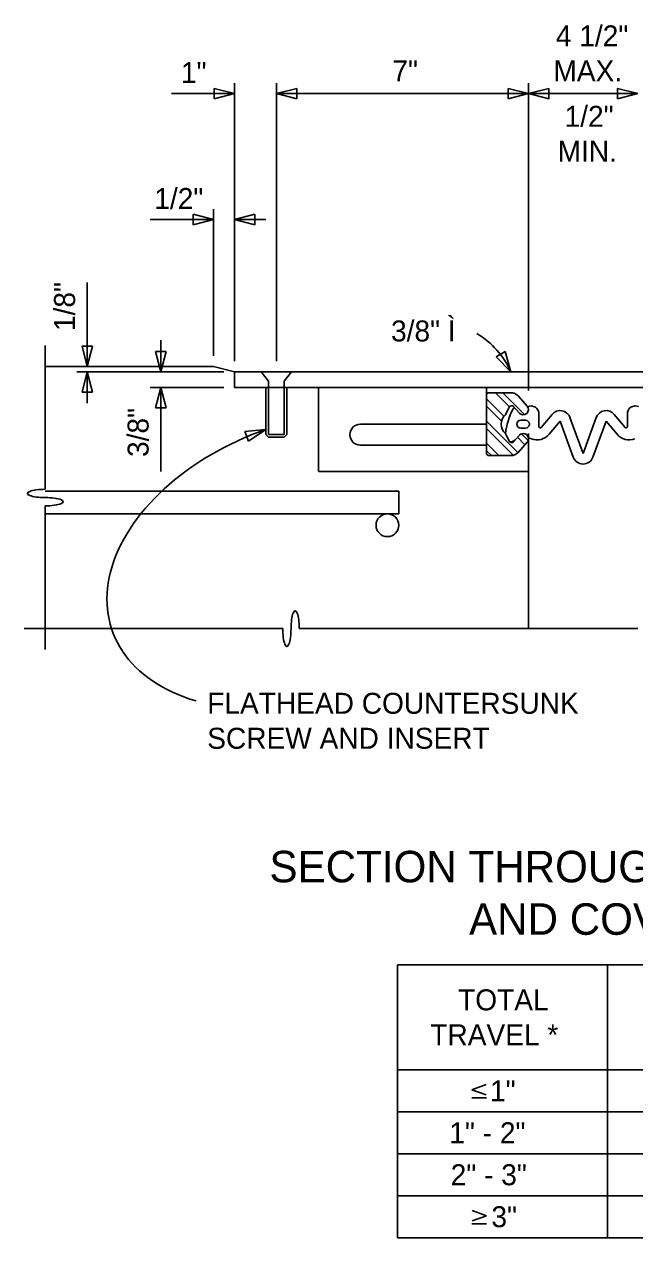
# Model space of a CAD drawing. Extents: x 19590 to 20151, y 19944 to 20103.
# Drawn here: x 19678.31 to 19691.75, y 20042.3 to 20069.04 of the extents above; entities that cross this region are included whole.
import ezdxf

# ---------------------------------------------------------------- set-up
doc = ezdxf.new("R2010")
doc.units = 0
for name, color, linetype in [('B-O', 7, 'Continuous'), ('Default', 7, 'Continuous'), ('DETAIL_PR', 7, 'Continuous'), ('DETAIL_TEXT_DIMEN_PR', 7, 'Continuous'), ('Level 1', 7, 'Continuous'), ('Sheet_Label_Str_Wt0', 7, 'Continuous')]:
    doc.layers.add(name, color=color, linetype=linetype)

# ---------------------------------------------------------------- blocks, each defined once
blk = doc.blocks.new('_X7')
at = {"layer": 'Default'}
for p, q in [((8.051, 16.889), (8.594, 17.433)), ((8.426, 17.08), (8.778, 17.433)), ((8.56, 16.847), (8.995, 17.282)), ((8.622, 16.724), (8.995, 17.098)), ((8.213, 15.947), (8.995, 16.729)), ((7.96, 16.247), (8.125, 16.412)), ((8.04, 16.142), (8.224, 16.326)), ((8.329, 15.879), (8.995, 16.545)), ((8.689, 15.87), (8.995, 16.177)), ((8.873, 15.87), (8.995, 15.993))]:
    blk.add_line(p, q, dxfattribs=at)

msp = doc.modelspace()

# ---------------------------------------------------------------- linework, layer by layer
at = {"layer": 'B-O'}
msp.add_line((19684.787, 20061.036), (19688.545, 20061.036), dxfattribs=at)
msp.add_line((19684.787, 20061.036), (19688.545, 20061.036), dxfattribs=at)
at = {"layer": 'DETAIL_PR'}
for p, q in [((19682.475, 20061.498), (19678.775, 20061.498)), ((19682.475, 20061.498), (19678.775, 20061.498)), ((19682.937, 20061.383), (19682.475, 20061.498)), ((19682.937, 20061.383), (19682.475, 20061.498)), ((19682.937, 20061.036), (19682.937, 20061.383)), ((19682.937, 20061.383), (19699.472, 20061.383)), ((19682.937, 20061.036), (19682.937, 20061.383)), ((19682.937, 20061.383), (19699.472, 20061.383)), ((19683.689, 20061.176), (19683.531, 20061.383)), ((19683.531, 20061.383), (19684.194, 20061.383)), ((19683.689, 20061.176), (19683.531, 20061.383)), ((19683.531, 20061.383), (19684.194, 20061.383)), ((19684.194, 20061.383), (19684.036, 20061.176)), ((19684.194, 20061.383), (19684.036, 20061.176)), ((19683.689, 20059.995), (19683.689, 20061.176)), ((19683.689, 20059.995), (19683.689, 20061.176)), ((19684.036, 20061.176), (19684.036, 20059.995)), ((19684.036, 20061.176), (19684.036, 20059.995)), ((19699.587, 20061.036), (19682.937, 20061.036)), ((19699.587, 20061.036), (19682.937, 20061.036)), ((19683.631, 20059.995), (19683.631, 20061.036)), ((19683.631, 20059.995), (19683.631, 20061.036)), ((19684.094, 20061.036), (19684.094, 20059.995)), ((19684.094, 20061.036), (19684.094, 20059.995)), ((19684.787, 20059.186), (19684.787, 20061.036)), ((19684.787, 20059.186), (19684.787, 20061.036)), ((19688.487, 20060.862), (19688.487, 20061.036)), ((19688.487, 20060.862), (19688.487, 20061.036)), ((19688.487, 20060.862), (19688.487, 20060.226)), ((19688.487, 20060.862), (19688.487, 20060.226)), ((19689.019, 20060.92), (19688.545, 20060.92)), ((19689.019, 20060.92), (19688.545, 20060.92)), ((19688.904, 20060.43), (19688.991, 20060.602)), ((19688.904, 20060.43), (19688.991, 20060.602)), ((19689.21, 20060.473), (19689.085, 20060.614)), ((19689.21, 20060.473), (19689.085, 20060.614)), ((19689.383, 20060.626), (19689.192, 20060.842)), ((19689.383, 20060.626), (19689.192, 20060.842)), ((19689.242, 20060.313), (19689.347, 20060.313)), ((19689.242, 20060.313), (19689.347, 20060.313)), ((19689.64, 20060.443), (19689.64, 20060.174)), ((19689.64, 20060.443), (19689.64, 20060.174)), ((19689.691, 20060.155), (19689.933, 20060.442)), ((19689.691, 20060.155), (19689.933, 20060.442)), ((19690.616, 20059.578), (19690.327, 20060.373)), ((19690.616, 20059.578), (19690.327, 20060.373)), ((19690.616, 20059.578), (19690.905, 20060.373)), ((19690.616, 20059.578), (19690.905, 20060.373)), ((19691.541, 20060.155), (19691.3, 20060.442)), ((19691.541, 20060.155), (19691.3, 20060.442)), ((19691.592, 20060.443), (19691.592, 20060.174)), ((19691.592, 20060.443), (19691.592, 20060.174)), ((19688.487, 20060.226), (19685.712, 20060.226)), ((19688.487, 20060.226), (19685.712, 20060.226)), ((19688.487, 20060.226), (19688.487, 20059.764)), ((19688.487, 20060.226), (19688.487, 20059.764)), ((19689.242, 20060.14), (19689.347, 20060.14)), ((19689.242, 20060.14), (19689.347, 20060.14)), ((19689.866, 20060.003), (19690.11, 20060.294)), ((19689.866, 20060.003), (19690.11, 20060.294)), ((19690.399, 20059.499), (19690.11, 20060.294)), ((19690.399, 20059.499), (19690.11, 20060.294)), ((19690.833, 20059.499), (19691.122, 20060.294)), ((19690.833, 20059.499), (19691.122, 20060.294)), ((19691.366, 20060.003), (19691.122, 20060.294)), ((19691.366, 20060.003), (19691.122, 20060.294)), ((19683.631, 20059.995), (19683.689, 20059.937)), ((19683.631, 20059.995), (19683.689, 20059.937)), ((19684.036, 20059.995), (19683.689, 20059.995)), ((19684.036, 20059.995), (19683.689, 20059.995)), ((19684.036, 20059.937), (19683.689, 20059.937)), ((19684.036, 20059.937), (19683.689, 20059.937)), ((19684.094, 20059.995), (19684.036, 20059.937)), ((19684.094, 20059.995), (19684.036, 20059.937)), ((19688.904, 20060.023), (19688.991, 20059.851)), ((19688.904, 20060.023), (19688.991, 20059.851)), ((19689.121, 20059.879), (19689.078, 20059.854)), ((19689.121, 20059.879), (19689.078, 20059.854)), ((19689.21, 20059.98), (19689.085, 20059.839)), ((19689.21, 20059.98), (19689.085, 20059.839)), ((19689.383, 20059.827), (19689.192, 20059.611)), ((19689.383, 20059.827), (19689.192, 20059.611)), ((19689.48, 20059.9), (19689.41, 20059.926)), ((19689.48, 20059.9), (19689.41, 20059.926)), ((19689.412, 20055.72), (19689.412, 20060.019)), ((19689.412, 20055.72), (19689.412, 20060.019)), ((19688.487, 20059.764), (19685.712, 20059.764)), ((19688.487, 20059.764), (19685.712, 20059.764)), ((19688.487, 20059.764), (19688.487, 20059.591)), ((19688.487, 20059.764), (19688.487, 20059.591)), ((19688.545, 20059.533), (19689.019, 20059.533)), ((19688.545, 20059.533), (19689.019, 20059.533)), ((19689.412, 20059.186), (19684.799, 20059.186)), ((19689.412, 20059.186), (19684.799, 20059.186)), ((19678.775, 20058.748), (19686.557, 20058.748)), ((19678.775, 20058.748), (19686.557, 20058.748)), ((19686.557, 20058.748), (19686.557, 20058.248)), ((19686.557, 20058.748), (19686.557, 20058.248)), ((19678.775, 20058.248), (19686.557, 20058.248)), ((19678.775, 20058.248), (19686.557, 20058.248))]:
    msp.add_line(p, q, dxfattribs=at)
msp.add_circle((19686.307, 20057.998), 0.25, dxfattribs=at)
msp.add_circle((19686.307, 20057.998), 0.25, dxfattribs=at)
for centre, radius, start, end in [((19688.545, 20060.862), 0.0578, 90, 180), ((19688.545, 20060.862), 0.0578, 90, 180), ((19689.019, 20060.689), 0.231, 41.462, 90), ((19689.019, 20060.689), 0.231, 41.462, 90), ((19689.042, 20060.576), 0.0578, 41.462, 153.1909), ((19689.042, 20060.576), 0.0578, 41.462, 153.1909), ((19689.125, 20060.533), 0.0578, 106.6655, 151.2528), ((19689.125, 20060.533), 0.0578, 106.6655, 151.2528), ((19689.297, 20060.549), 0.116, 221.462, 41.462), ((19689.297, 20060.549), 0.116, 221.462, 41.462), ((19689.468, 20060.456), 0.173, 355.6455, 115.2375), ((19689.468, 20060.456), 0.173, 355.6455, 115.2375), ((19691.765, 20060.456), 0.173, 64.7625, 184.3545), ((19691.765, 20060.456), 0.173, 64.7625, 184.3545), ((19689.081, 20060.226), 0.27, 131.1121, 228.8879), ((19689.081, 20060.226), 0.27, 131.1121, 228.8879), ((19690.291, 20059.893), 1.388, 151.2528, 175.0143), ((19690.291, 20059.893), 1.388, 151.2528, 175.0143), ((19689.242, 20060.226), 0.0867, 90, 270), ((19689.242, 20060.226), 0.0867, 90, 270), ((19689.347, 20060.226), 0.0867, 270, 90), ((19689.347, 20060.226), 0.0867, 270, 90), ((19690.11, 20060.294), 0.231, 19.9948, 140), ((19690.11, 20060.294), 0.231, 19.9948, 140), ((19691.122, 20060.294), 0.231, 40, 160.0052), ((19691.122, 20060.294), 0.231, 40, 160.0052), ((19685.712, 20059.995), 0.231, 90, 270), ((19685.712, 20059.995), 0.231, 90, 270), ((19689.669, 20060.174), 0.0289, 180, 320), ((19689.669, 20060.174), 0.0289, 180, 320), ((19691.563, 20060.174), 0.0289, 220, 0), ((19691.563, 20060.174), 0.0289, 220, 0), ((19689.042, 20059.877), 0.0578, 206.8091, 318.538), ((19689.042, 20059.877), 0.0578, 206.8091, 318.538), ((19689.02, 20059.954), 0.116, 258.4931, 300), ((19689.02, 20059.954), 0.116, 258.4931, 300), ((19689.297, 20059.904), 0.116, 0, 138.538), ((19689.297, 20059.904), 0.116, 0, 138.538), ((19689.297, 20059.904), 0.116, 318.538, 0), ((19689.297, 20059.904), 0.116, 318.538, 0), ((19689.6, 20060.226), 0.347, 249.847, 320), ((19689.6, 20060.226), 0.347, 249.847, 320), ((19691.632, 20060.226), 0.347, 220, 290.153), ((19691.632, 20060.226), 0.347, 220, 290.153), ((19688.545, 20059.591), 0.0578, 180, 270), ((19688.545, 20059.591), 0.0578, 180, 270), ((19689.019, 20059.764), 0.231, 270, 318.538), ((19689.019, 20059.764), 0.231, 270, 318.538), ((19690.616, 20059.578), 0.231, 200, 340), ((19690.616, 20059.578), 0.231, 200, 340)]:
    msp.add_arc(centre, radius, start, end, dxfattribs=at)
for centre, major_axis, ratio, start_param, end_param in [((19678.775, 20058.7), (0.395, 0), 0.230204, 1.570796, 4.712389), ((19678.775, 20058.7), (0.395, 0), 0.230204, 1.570796, 4.712389), ((19678.775, 20058.518), (0.395, 0), 0.230206, 4.712389, 7.853982), ((19678.775, 20058.518), (0.395, 0), 0.230206, 4.712389, 7.853982), ((19684.276, 20055.72), (0, -0.395), 0.230204, 1.570796, 4.712389), ((19684.276, 20055.72), (0, -0.395), 0.230204, 1.570796, 4.712389), ((19684.094, 20055.72), (0, -0.395), 0.230206, 4.712389, 7.853982), ((19684.094, 20055.72), (0, -0.395), 0.230206, 4.712389, 7.853982)]:
    msp.add_ellipse(centre, major_axis=major_axis, ratio=ratio, start_param=start_param, end_param=end_param, dxfattribs=at)
at = {"layer": 'DETAIL_TEXT_DIMEN_PR'}
for p, q in [((19682.49, 20067.395), (19682.49, 20067.626)), ((19682.49, 20067.626), (19682.937, 20067.511)), ((19682.49, 20067.395), (19682.49, 20067.626)), ((19682.49, 20067.626), (19682.937, 20067.511)), ((19682.937, 20061.614), (19682.937, 20067.742)), ((19682.937, 20061.614), (19682.937, 20067.742)), ((19683.862, 20061.614), (19683.862, 20067.742)), ((19683.862, 20061.614), (19683.862, 20067.742)), ((19684.31, 20067.626), (19683.862, 20067.511)), ((19684.31, 20067.626), (19683.862, 20067.511)), ((19684.31, 20067.395), (19684.31, 20067.626)), ((19684.31, 20067.395), (19684.31, 20067.626)), ((19688.965, 20067.395), (19688.965, 20067.626)), ((19688.965, 20067.626), (19689.412, 20067.511)), ((19688.965, 20067.395), (19688.965, 20067.626)), ((19688.965, 20067.626), (19689.412, 20067.511)), ((19689.412, 20060.967), (19689.412, 20067.742)), ((19689.412, 20060.967), (19689.412, 20067.742)), ((19689.86, 20067.626), (19689.412, 20067.511)), ((19689.86, 20067.626), (19689.412, 20067.511)), ((19689.86, 20067.395), (19689.86, 20067.626)), ((19689.86, 20067.395), (19689.86, 20067.626)), ((19691.372, 20067.395), (19691.372, 20067.626)), ((19691.372, 20067.626), (19691.82, 20067.511)), ((19691.372, 20067.395), (19691.372, 20067.626)), ((19691.372, 20067.626), (19691.82, 20067.511)), ((19682.937, 20067.511), (19682.49, 20067.395)), ((19682.937, 20067.511), (19682.49, 20067.395)), ((19689.412, 20067.511), (19683.862, 20067.511)), ((19683.862, 20067.511), (19684.31, 20067.395)), ((19689.412, 20067.511), (19683.862, 20067.511)), ((19683.862, 20067.511), (19684.31, 20067.395)), ((19689.412, 20067.511), (19688.965, 20067.395)), ((19689.412, 20067.511), (19688.965, 20067.395)), ((19689.412, 20067.511), (19691.82, 20067.511)), ((19689.412, 20067.511), (19689.86, 20067.395)), ((19689.412, 20067.511), (19691.82, 20067.511)), ((19689.412, 20067.511), (19689.86, 20067.395)), ((19691.82, 20067.511), (19691.372, 20067.395)), ((19691.82, 20067.511), (19691.372, 20067.395)), ((19682.475, 20061.73), (19682.475, 20064.967)), ((19682.475, 20061.73), (19682.475, 20064.967)), ((19682.027, 20064.62), (19682.027, 20064.851)), ((19682.027, 20064.851), (19682.475, 20064.736)), ((19682.027, 20064.62), (19682.027, 20064.851)), ((19682.027, 20064.851), (19682.475, 20064.736)), ((19682.475, 20064.736), (19682.027, 20064.62)), ((19682.475, 20064.736), (19682.027, 20064.62)), ((19683.385, 20064.851), (19682.937, 20064.736)), ((19683.385, 20064.851), (19682.937, 20064.736)), ((19682.937, 20064.736), (19683.385, 20064.62)), ((19682.937, 20064.736), (19683.385, 20064.62)), ((19683.385, 20064.62), (19683.385, 20064.851)), ((19683.385, 20064.62), (19683.385, 20064.851)), ((19678.775, 20058.791), (19678.775, 20061.961)), ((19678.775, 20058.791), (19678.775, 20061.961)), ((19679.584, 20061.946), (19679.816, 20061.946)), ((19679.7, 20061.498), (19679.584, 20061.946)), ((19679.584, 20061.946), (19679.816, 20061.946)), ((19679.7, 20061.498), (19679.584, 20061.946)), ((19679.816, 20061.946), (19679.7, 20061.498)), ((19679.816, 20061.946), (19679.7, 20061.498)), ((19681.203, 20061.831), (19681.434, 20061.831)), ((19681.319, 20061.383), (19681.203, 20061.831)), ((19681.203, 20061.831), (19681.434, 20061.831)), ((19681.319, 20061.383), (19681.203, 20061.831)), ((19681.434, 20061.831), (19681.319, 20061.383)), ((19681.434, 20061.831), (19681.319, 20061.383)), ((19688.699, 20061.711), (19688.899, 20061.828)), ((19688.699, 20061.711), (19688.899, 20061.828)), ((19689.026, 20061.383), (19688.699, 20061.711)), ((19689.026, 20061.383), (19688.699, 20061.711)), ((19688.899, 20061.828), (19689.026, 20061.383)), ((19688.899, 20061.828), (19689.026, 20061.383)), ((19682.706, 20061.383), (19679.469, 20061.383)), ((19682.706, 20061.383), (19679.469, 20061.383)), ((19679.584, 20060.935), (19679.7, 20061.383)), ((19679.584, 20060.935), (19679.7, 20061.383)), ((19679.7, 20061.383), (19679.816, 20060.935)), ((19679.7, 20061.383), (19679.816, 20060.935)), ((19679.816, 20060.935), (19679.584, 20060.935)), ((19679.816, 20060.935), (19679.584, 20060.935)), ((19682.706, 20061.036), (19681.087, 20061.036)), ((19682.706, 20061.036), (19681.087, 20061.036)), ((19681.203, 20060.588), (19681.319, 20061.036)), ((19681.203, 20060.588), (19681.319, 20061.036)), ((19681.319, 20061.036), (19681.434, 20060.588)), ((19681.319, 20061.036), (19681.434, 20060.588)), ((19681.434, 20060.588), (19681.203, 20060.588)), ((19681.434, 20060.588), (19681.203, 20060.588)), ((19683.171, 20060.066), (19683.631, 20060.112)), ((19683.171, 20060.066), (19683.631, 20060.112)), ((19683.251, 20059.849), (19683.171, 20060.066)), ((19683.251, 20059.849), (19683.171, 20060.066)), ((19683.631, 20060.112), (19683.251, 20059.849)), ((19683.631, 20060.112), (19683.251, 20059.849)), ((19678.775, 20055.258), (19678.775, 20058.427)), ((19678.775, 20055.258), (19678.775, 20058.427)), ((19678.312, 20055.72), (19684.003, 20055.72)), ((19678.312, 20055.72), (19684.003, 20055.72)), ((19689.412, 20055.72), (19684.367, 20055.72)), ((19689.412, 20055.72), (19684.367, 20055.72)), ((19686.526, 20048.311), (19686.526, 20042.298)), ((19686.526, 20048.311), (19700.401, 20048.311)), ((19686.526, 20048.311), (19686.526, 20042.298)), ((19686.526, 20048.311), (19700.401, 20048.311)), ((19691.151, 20048.311), (19691.151, 20042.298)), ((19691.151, 20048.311), (19691.151, 20042.298)), ((19686.526, 20045.998), (19700.401, 20045.998)), ((19686.526, 20045.998), (19700.401, 20045.998)), ((19688.166, 20045.559), (19688.481, 20045.674)), ((19688.166, 20045.559), (19688.481, 20045.674)), ((19688.166, 20045.559), (19688.481, 20045.445)), ((19688.166, 20045.559), (19688.481, 20045.445)), ((19688.166, 20045.382), (19688.49, 20045.382)), ((19688.166, 20045.382), (19688.49, 20045.382)), ((19686.526, 20045.073), (19700.401, 20045.073)), ((19686.526, 20045.073), (19700.401, 20045.073)), ((19686.526, 20044.148), (19700.401, 20044.148)), ((19686.526, 20044.148), (19700.401, 20044.148)), ((19686.526, 20043.223), (19700.401, 20043.223)), ((19686.526, 20043.223), (19700.401, 20043.223)), ((19688.49, 20042.784), (19688.175, 20042.899)), ((19688.49, 20042.784), (19688.175, 20042.899)), ((19688.49, 20042.784), (19688.175, 20042.67)), ((19688.49, 20042.784), (19688.175, 20042.67)), ((19688.49, 20042.607), (19688.166, 20042.607)), ((19688.49, 20042.607), (19688.166, 20042.607)), ((19686.526, 20042.298), (19700.401, 20042.298)), ((19686.526, 20042.298), (19700.401, 20042.298))]:
    msp.add_line(p, q, dxfattribs=at)
at = {"layer": 'Level 1'}
for p, q in [((19681.55, 20067.511), (19682.937, 20067.511)), ((19681.55, 20067.511), (19682.937, 20067.511)), ((19681.087, 20064.736), (19682.475, 20064.736)), ((19681.087, 20064.736), (19682.475, 20064.736)), ((19683.631, 20064.736), (19682.937, 20064.736)), ((19683.631, 20064.736), (19682.937, 20064.736)), ((19679.7, 20061.498), (19679.7, 20063.348)), ((19679.7, 20061.498), (19679.7, 20063.348)), ((19681.319, 20062.076), (19681.319, 20061.383)), ((19681.319, 20062.076), (19681.319, 20061.383)), ((19679.7, 20060.689), (19679.7, 20061.383)), ((19679.7, 20060.689), (19679.7, 20061.383)), ((19681.319, 20061.036), (19681.319, 20059.186)), ((19681.319, 20061.036), (19681.319, 20059.186)), ((19689.412, 20055.72), (19691.82, 20055.72)), ((19689.412, 20055.72), (19691.82, 20055.72))]:
    msp.add_line(p, q, dxfattribs=at)
msp.add_arc((19687.32, 20060.615), 1.87, 24.225, 59.1642, dxfattribs=at)
msp.add_arc((19687.32, 20060.615), 1.87, 24.225, 59.1642, dxfattribs=at)
msp.add_ellipse((19684.645, 20057.22), major_axis=(4.397, 1.542), ratio=0.657723, start_param=1.570796, end_param=3.885568, dxfattribs=at)
msp.add_ellipse((19684.645, 20057.22), major_axis=(4.397, 1.542), ratio=0.657723, start_param=1.570796, end_param=3.885568, dxfattribs=at)

# ---------------------------------------------------------------- block references
at = {"layer": 'DETAIL_PR', "xscale": 0.8880107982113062, "yscale": -0.8880107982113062, "rotation": 180}
msp.add_blockref('_X7', (19696.475, 20045.44), dxfattribs=at)
msp.add_blockref('_X7', (19696.475, 20045.44), dxfattribs=at)

# ---------------------------------------------------------------- texts
at = {"layer": 'DETAIL_TEXT_DIMEN_PR'}
for s, height, p in [('4 1/2"', 0.4625, (19690.016, 20068.551)), ('4 1/2"', 0.4625, (19690.016, 20068.551)), ('1"', 0.4625, (19681.761, 20067.742)), ('1"', 0.4625, (19681.761, 20067.742)), ('7"', 0.4625, (19686.416, 20067.781)), ('7"', 0.4625, (19686.416, 20067.781)), ('MAX.', 0.4625, (19689.962, 20067.781)), ('MAX.', 0.4625, (19689.962, 20067.781)), ('1/2"', 0.4625, (19690.208, 20066.779)), ('1/2"', 0.4625, (19690.208, 20066.779)), ('MIN.', 0.4625, (19690.055, 20066.008)), ('MIN.', 0.4625, (19690.055, 20066.008)), ('1/2"', 0.4625, (19681.175, 20064.967)), ('1/2"', 0.4625, (19681.175, 20064.967)), ('FLATHEAD COUNTERSUNK', 0.4625, (19682.34, 20053.844)), ('FLATHEAD COUNTERSUNK', 0.4625, (19682.34, 20053.844)), ('SCREW AND INSERT', 0.4625, (19682.34, 20053.073)), ('SCREW AND INSERT', 0.4625, (19682.34, 20053.073)), ('SECTION THROUGH EXPANSION JOINT', 0.69385, (19683.71, 20050.13)), ('SECTION THROUGH EXPANSION JOINT', 0.69385, (19683.71, 20050.13)), ('AND COVER PLATE', 0.69385, (19688.104, 20048.974)), ('AND COVER PLATE', 0.69385, (19688.104, 20048.974))]:
    msp.add_text(s, height=height, dxfattribs=at).set_placement(p)
for s, rotation, p in [('1/8"', 90, (19679.43, 20062.279)), ('1/8"', 90, (19679.43, 20062.279)), ('3/8"', 90, (19681.049, 20059.504)), ('3/8"', 90, (19681.049, 20059.504)), ('TOTAL', 0, (19687.863, 20047.309)), ('TOTAL', 0, (19687.863, 20047.309)), ('TRAVEL *', 0, (19687.251, 20046.538)), ('TRAVEL *', 0, (19687.251, 20046.538)), (' 1"', 0, (19688.394, 20045.305)), (' 1"', 0, (19688.394, 20045.305)), ('1" - 2"', 0, (19687.67, 20044.38)), ('1" - 2"', 0, (19687.67, 20044.38)), ('2" - 3"', 0, (19687.7, 20043.455)), ('2" - 3"', 0, (19687.7, 20043.455)), (' 3"', 0, (19688.425, 20042.53)), (' 3"', 0, (19688.425, 20042.53))]:
    msp.add_text(s, height=0.4625, rotation=rotation, dxfattribs=at).set_placement(p)
at = {"layer": 'Sheet_Label_Str_Wt0'}
msp.add_text('3/8" Ì', height=0.4625, dxfattribs=at).set_placement((19686.387, 20062.049))
msp.add_text('3/8" Ì', height=0.4625, dxfattribs=at).set_placement((19686.387, 20062.049))

doc.saveas('drawing.dxf')
